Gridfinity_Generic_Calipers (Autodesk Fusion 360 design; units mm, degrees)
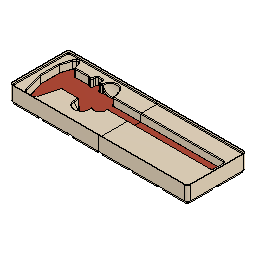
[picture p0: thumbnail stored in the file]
work_plane "WorkPlane1" AlongDistance 0
sketch "Base plate sketch" plane through (0, 0, 0) normal (0, 0, 1) x axis (1, 0, 0)
  line L1 (41.75, -0.25) -> (-0.25, -0.25)
  line L2 (41.75, 41.75) -> (41.75, -0.25)
  line L3 (-0.25, 41.75) -> (41.75, 41.75)
  line L4 (-0.25, -0.25) -> (-0.25, 41.75)
  point P1 (0, 0)
  point P2 (-0.25, -0.25)
  point P5 (-0.25, 41.75)
  point P3 (41.75, -0.25)
  point P4 (41.75, 41.75)
  horizontal L1
  vertical L2
  horizontal L3
  vertical L4
  dimension "d26" distance P1 P2 = 0.25
  dimension "d27" distance P1 P5 = 0.25
  dimension "d28" distance P2 P3 = 42
  dimension "d29" distance P3 P4 = 42
extrude "Extrude1" new body sketch "Base plate sketch" against normal blind 2.4 (magnitude of "-( 2.40 mm )") bodies "Base"
fillet "Fillet1" radius 4
chamfer "Chamfer1" distance 2.4
extrude "Extrude2" add of existing geometry blind 2.6
chamfer "Chamfer2" distance 0.8
rectangular_pattern "R-Pattern1" uSpaceDistance 42 vSpaceDistance 42 bodies "Base (1)", "Base (2)", "Base (3)", "Base (4)", "Base (5)", "Base (6)", "Base (7)", "Base (8)"
sketch "Simple box sketch" plane through (0, 0, 0) normal (0, 0, 1) x axis (1, 0, 0)
  line L1 (251.5, 0) -> (0, 0)
  line L2 (251.5, 83.5) -> (251.5, 0)
  line L3 (0, 83.5) -> (251.5, 83.5)
  line L4 (0, 0) -> (0, 83.5)
  point P1 (0, 0)
  point P2 (0, 0)
  point P3 (251.5, 0)
  point P4 (251.5, 83.5)
  horizontal L1
  vertical L2
  horizontal L3
  vertical L4
  coincident P1 L4
  coincident P1 L1
  dimension "d42" distance P2 P3 = 251.5
  dimension "d43" distance P3 P4 = 83.5
extrude "Extrude3" new body sketch "Simple box sketch" along normal blind 16
fillet "Fillet2" radius 3.75
work_plane "WorkPlane2" AlongDistance 16
sketch "Simple box at point sketch" plane through (0, 0, 16) normal (0, 0, 1) x axis (1, 0, 0)
  line L1 (251.5, 0) -> (0, 0)
  line L2 (251.5, 83.5) -> (251.5, 0)
  line L3 (0, 83.5) -> (251.5, 83.5)
  line L4 (0, 0) -> (0, 83.5)
  point P1 (0, 0)
  point P2 (0, 0)
  point P3 (251.5, 0)
  point P4 (251.5, 83.5)
  horizontal L1
  vertical L2
  horizontal L3
  vertical L4
  coincident P1 L4
  coincident P1 L1
  dimension "d49" distance P2 P3 = 251.5
  dimension "d50" distance P3 P4 = 83.5
extrude "Extrude4" new body sketch "Simple box at point sketch" along normal blind 4.4 bodies "Lip body"
fillet "Fillet3" radius 3.75
work_plane "WorkPlane3" AlongDistance 21
sketch "Base plate sketch (1)" plane through (0, 0, 21) normal (0, 0, 1) x axis (1, 0, 0)
  line L1 (252, -0.5) -> (-0.5, -0.5)
  line L2 (252, 84) -> (252, -0.5)
  line L3 (-0.5, 84) -> (252, 84)
  line L4 (-0.5, -0.5) -> (-0.5, 84)
  point P1 (0, 0)
  point P2 (-0.5, -0.5)
  point P5 (-0.5, 84)
  point P3 (252, -0.5)
  point P4 (252, 84)
  horizontal L1
  vertical L2
  horizontal L3
  vertical L4
  dimension "d56" distance P1 P2 = 0.5
  dimension "d57" distance P1 P5 = 0.5
  dimension "d58" distance P2 P3 = 252.5
  dimension "d59" distance P3 P4 = 84.5
extrude "Extrude5" new body sketch "Base plate sketch (1)" against normal blind 2.4 (magnitude of "-( 2.40 mm )") bodies "Lip cutout"
fillet "Fillet4" radius 4.25
chamfer "Chamfer3" distance 2.4
extrude "Extrude6" add of existing geometry blind 2.6
work_plane "WorkPlane4" AlongDistance 0
sketch "Lip top chamfer" plane through (0, 0, 20.4) normal (0, 0, 1) x axis (1, 0, 0)
  line L1 (251.5, 0) -> (0, 0)
  line L2 (251.5, 83.5) -> (251.5, 0)
  line L3 (0, 83.5) -> (251.5, 83.5)
  line L4 (0, 0) -> (0, 83.5)
  point P1 (0, 0)
  point P2 (0, 0)
  point P3 (251.5, 0)
  point P4 (251.5, 83.5)
  horizontal L1
  vertical L2
  horizontal L3
  vertical L4
  coincident P1 L4
  coincident P1 L1
  dimension "d68" distance P2 P3 = 251.5
  dimension "d69" distance P3 P4 = 83.5
extrude "Extrude7" new body sketch "Lip top chamfer" against normal blind 0.6 (magnitude of "-( 0.60 mm )")
combine "Combine1" bodies "Lip cutout"
work_plane "WorkPlane5" AlongDistance 16
sketch "Simple box at point sketch (1)" plane through (0, 0, 16) normal (0, 0, 1) x axis (1, 0, 0)
  line L1 (250.3, 1.2) -> (1.2, 1.2)
  line L2 (250.3, 82.3) -> (250.3, 1.2)
  line L3 (1.2, 82.3) -> (250.3, 82.3)
  line L4 (1.2, 1.2) -> (1.2, 82.3)
  point P1 (0, 0)
  point P2 (1.2, 1.2)
  point P5 (1.2, 82.3)
  point P3 (250.3, 1.2)
  point P4 (250.3, 82.3)
  horizontal L1
  vertical L2
  horizontal L3
  vertical L4
  dimension "d73" distance P1 P2 = 1.2
  dimension "d74" distance P1 P5 = 1.2
  dimension "d75" distance P2 P3 = 249.1
  dimension "d76" distance P3 P4 = 81.1
extrude "Extrude8" new body sketch "Simple box at point sketch (1)" along normal blind 2.55
fillet "Fillet5" radius 2.55
chamfer "Chamfer4" distance 2.55
combine "Combine2"
combine "Combine3" bodies "Lip body"
work_plane "WorkPlane6" AlongDistance 0
sketch "Base clearance cut sketch" plane through (0, 0, 0) normal (0, 0, 1) x axis (1, 0, 0)
  line L1 (247.75, 0) -> (3.75, 0)
  line L2 (251.5, 79.75) -> (251.5, 3.75)
  line L3 (3.75, 83.5) -> (247.75, 83.5)
  line L4 (0, 3.75) -> (0, 79.75)
  line L5 (261.5, 79.75) -> (261.5, 3.75)
  line L6 (3.75, 93.5) -> (247.75, 93.5)
  line L7 (-10, 3.75) -> (-10, 79.75)
  line L8 (247.75, -10) -> (3.75, -10)
  arc A1 centre (247.75, 3.75) radius 3.75 clockwise from (251.5, 3.75) to (247.75, 0)
  arc A2 centre (247.75, 79.75) radius 3.75 clockwise from (247.75, 83.5) to (251.5, 79.75)
  arc A3 centre (3.75, 79.75) radius 3.75 clockwise from (0, 79.75) to (3.75, 83.5)
  arc A4 centre (3.75, 3.75) radius 3.75 clockwise from (3.75, 0) to (0, 3.75)
  arc A5 centre (247.75, 3.75) radius 13.75 clockwise from (261.5, 3.75) to (247.75, -10)
  arc A6 centre (247.75, 79.75) radius 13.75 clockwise from (247.75, 93.5) to (261.5, 79.75)
  arc A7 centre (3.75, 79.75) radius 13.75 clockwise from (-10, 79.75) to (3.75, 93.5)
  arc A8 centre (3.75, 3.75) radius 13.75 clockwise from (3.75, -10) to (-10, 3.75)
  point P1 (0, 0)
  point P3 (251.5, 0)
  point P4 (251.5, 83.5)
  point P2 (0, 0)
  horizontal L1
  vertical L2
  horizontal L3
  vertical L4
  coincident P1 L4
  coincident P1 L1
  coincident P3 L1
  coincident P3 L2
  tangent L1 A1
  tangent L2 A1
  coincident P4 L2
  coincident P4 L3
  tangent L2 A2
  tangent L3 A2
  tangent L3 A3
  tangent L4 A3
  coincident P2 L4
  coincident P2 L1
  tangent L4 A4
  tangent L1 A4
  equal A1 A2
  equal A2 A3
  equal A3 A4
  dimension "d83" distance P2 P3 = 251.5
  dimension "d84" distance P3 P4 = 83.5
  dimension "d85" radius A1 = 3.75
  dimension "d86" = 10
extrude "Extrude9" cut sketch "Base clearance cut sketch" along normal blind 1000 and against normal blind 1000
combine "Combine4" bodies "Base (1)", "Base (2)", "Base (3)", "Base (4)", "Base (5)", "Base (6)", "Base (7)", "Base (8)"
canvas "Canvas1"
sketch "Sketch1" plane through (0, 0, 16) normal (0, 0, 1) x axis (1, 0, 0)
  line L1 (-92.5619, 18.2001) -> (-95.3903, 21.0285)
  line L2 (-89.9737, 8.5409) -> (-92.5619, 18.2001)
  line L3 (-68.9737, 8.5409) -> (-89.9737, 8.5409)
  line L4 (-67.9737, 7.5409) -> (-68.9737, 8.5409)
  line L5 (-61.9737, 7.5409) -> (-67.9737, 7.5409)
  line L6 (-61.9737, 14.5409) -> (-61.9737, 7.5409)
  line L7 (-54.9737, 14.5409) -> (-61.9737, 14.5409)
  line L8 (-54.9737, 7.5409) -> (-54.9737, 14.5409)
  line L9 (-48.9737, 7.5409) -> (-54.9737, 7.5409)
  line L10 (-47.9737, 8.5409) -> (-48.9737, 7.5409)
  line L11 (-27.9737, 8.5409) -> (-47.9737, 8.5409)
  line L12 (-98.6042, 17.1983) -> (-95.3903, 21.0285)
  line L13 (-102.9923, 3.6933) -> (-98.6042, 17.1983)
  line L14 (-102.9923, -22.5992) -> (-102.9923, 3.6933)
  line L15 (-95.309, -50.1366) -> (-102.9923, -22.5992)
  line L16 (-88.4425, -55.2852) -> (-95.309, -50.1366)
  line L17 (-82.0045, -50.1033) -> (-88.4425, -55.2852)
  line L18 (-74.757, -22.5735) -> (-82.0045, -50.1033)
  line L19 (-50.257, -22.5735) -> (-74.757, -22.5735)
  curve K1 (-28.5837, -23.1562) -> (-50.257, -22.5735)
  line L20 (-18.4991, -15.952) -> (131.0263, -15.952)
  line L21 (131.0263, 0.048) -> (131.0263, -15.952)
  line L22 (-27.9737, 0.048) -> (131.0263, 0.048)
  line L23 (-27.9737, 8.5409) -> (-27.9737, 0.048)
  curve K2 (-28.0801, -24.0202) -> (-50.2799, -23.5735)
  line L24 (-50.2799, -23.5735) -> (-73.9862, -23.5735)
  line L25 (-73.9862, -23.5735) -> (-81.1212, -50.676)
  line L26 (-81.1212, -50.676) -> (-88.4207, -56.5514)
  line L27 (-88.4207, -56.5514) -> (-96.1809, -50.7327)
  line L28 (-96.1809, -50.7327) -> (-103.9923, -22.7361)
  line L29 (-103.9923, -22.7361) -> (-103.9923, 3.8517)
  line L30 (-103.9923, 3.8517) -> (-99.4952, 17.6922)
  line L31 (-99.4952, 17.6922) -> (-95.4549, 22.5073)
  line L32 (-91.6653, 18.7177) -> (-95.4549, 22.5073)
  line L33 (-89.2064, 9.5409) -> (-91.6653, 18.7177)
  line L34 (-68.5595, 9.5409) -> (-89.2064, 9.5409)
  line L35 (-67.5595, 8.5409) -> (-68.5595, 9.5409)
  line L36 (-62.9737, 8.5409) -> (-67.5595, 8.5409)
  line L37 (-62.9737, 15.5409) -> (-62.9737, 8.5409)
  line L38 (-53.9737, 15.5409) -> (-62.9737, 15.5409)
  line L39 (-53.9737, 8.5409) -> (-53.9737, 15.5409)
  line L40 (-49.3879, 8.5409) -> (-53.9737, 8.5409)
  line L41 (-48.3879, 9.5409) -> (-49.3879, 8.5409)
  line L42 (-26.9737, 9.5409) -> (-48.3879, 9.5409)
  line L43 (-26.9737, 9.5409) -> (-26.9737, 1.048)
  line L44 (-26.9737, 1.048) -> (132.0263, 1.048)
  line L45 (132.0263, 1.048) -> (132.0263, -16.952)
  line L46 (-18.7439, -16.952) -> (132.0263, -16.952)
  line L47 (-38.5837, 9.6319) -> (-38.5837, -30.3681)
  line L48 (-28.5837, 9.6319) -> (-28.5837, -30.3681)
  line L49 (-48.5837, 9.6319) -> (-48.5837, -30.3681)
  line L50 (-38.5837, -40.3681) -> (-38.5837, -30.3681)
  line L51 (-38.5837, 19.6319) -> (-38.5837, 9.6319)
  line L52 (135.75, -57.8) -> (-108.25, -57.8)
  line L53 (138.3, 20.75) -> (138.3, -55.25)
  line L54 (-108.25, 23.3) -> (135.75, 23.3)
  line L55 (-110.8, -55.25) -> (-110.8, 20.75)
  circle C1 centre (-23.0682, -20.2165) radius 6.25
  circle C2 centre (-23.0682, -20.2165) radius 7.25
  circle C3 centre (-38.5837, -30.3681) radius 10
  circle C4 centre (-38.5837, 9.6319) radius 10
  arc A1 centre (135.75, -55.25) radius 2.55 clockwise from (138.3, -55.25) to (135.75, -57.8)
  arc A2 centre (135.75, 20.75) radius 2.55 clockwise from (135.75, 23.3) to (138.3, 20.75)
  arc A3 centre (-108.25, 20.75) radius 2.55 clockwise from (-110.8, 20.75) to (-108.25, 23.3)
  arc A4 centre (-108.25, -55.25) radius 2.55 clockwise from (-108.25, -57.8) to (-110.8, -55.25)
  point P26 (-28.5837, -23.1562)
  point P29 (-18.4991, -15.952)
  point P58 (-38.5837, -30.3681)
  point P59 (-38.5837, -30.3681)
  point P60 (-38.5837, 9.6319)
  point P61 (-38.5837, 9.6319)
  point P63 (-28.5837, 9.6319)
  point P65 (-48.5837, 9.6319)
  point P64 (-48.5837, -30.3681)
  point P62 (-28.5837, -30.3681)
  point P66 (-38.5837, -30.3681)
  point P67 (-38.5837, -40.3681)
  point P68 (-38.5837, 9.6319)
  point P69 (-38.5837, 19.6319)
  point P9 (-54.9737, 14.5409)
  point P10 (-54.9737, 7.5409)
  point P8 (-61.9737, 14.5409)
  point P11 (-48.9737, 7.5409)
  point P6 (-67.9737, 7.5409)
  point P7 (-61.9737, 7.5409)
  point P5 (-68.9737, 8.5409)
  point P4 (-89.9737, 8.5409)
  point P12 (-47.9737, 8.5409)
  point P13 (-27.9737, 8.5409)
  point P3 (-92.5619, 18.2001)
  point P2 (-95.3903, 21.0285)
  point P14 (-98.6042, 17.1983)
  point P15 (-102.9923, 3.6933)
  point P20 (-74.757, -22.5735)
  point P21 (-50.257, -22.5735)
  point P28 (131.0263, -15.952)
  point P30 (131.0263, 0.048)
  point P31 (-27.9737, 0.048)
  horizontal L3
  parallel L3 L5
  perpendicular L5 L6
  perpendicular L6 L7
  perpendicular L7 L8
  perpendicular L8 L9
  perpendicular L8 L11
  collinear L5 L9
  vertical L14
  horizontal L19
  coincident P26 C1
  coincident C1 P29
  horizontal L20
  perpendicular L20 L21
  perpendicular L21 L22
  vertical L23
  coincident P58 P59
  vertical L47
  coincident P60 P61
  equal C3 C4
  coincident C4 P63
  coincident C4 P65
  coincident C3 P64
  coincident C3 P62
  coincident P58 P66
  coincident C3 P67
  parallel L47 L50
  coincident P61 P68
  coincident C4 P69
  perpendicular L42 L51
  coincident P26 L48
  dimension "d1" distance L9 L11 = 1
  dimension "d2" distance P9 P10 = 7
  dimension "d3" distance P8 P9 = 7
  dimension "d4" distance P10 P11 = 6
  dimension "d5" distance P6 P7 = 6
  dimension "d6" distance P5 P6 = 1 (= "d1")
  dimension "d7" distance P4 P5 = 21
  dimension "d8" angle L4 L5 = 135
  dimension "d9" angle L9 L10 = 135
  dimension "d10" distance P12 P13 = 20
  dimension "d11" angle L2 L3 = 105
  dimension "d12" angle L1 L2 = 150
  dimension "d13" distance P3 P4 = 10
  dimension "d14" distance P2 P3 = 4
  dimension "d15" angle L1 L12 = 85
  dimension "d16" distance P2 P14 = 5
  dimension "d17" angle L12 L13 = 158
  dimension "d18" distance P14 P15 = 14.2
  dimension "d19" distance P20 P21 = 24.5
  dimension "d20" diameter C1 = 12.5
  dimension "d21" distance P28 P30 = 16
  dimension "d22" distance P30 P31 = 159
  dimension "d24" = 1
  dimension "d94" = 1
  dimension "d95" diameter C3 = 20
  dimension "d96" = 10 (= "d95 / 2")
  dimension "d97" = -10 (= "-d96")
  dimension "d98" distance P59 P60 = 40
extrude "Extrude1" cut sketch "Sketch1" profile of C2 L30 L27 L26 L35 L34 K2 L31 L32 L25 L24 L36 L29 L45 L42 L40 L37 L28 L38 L39 L44 L46 L43 L33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 against normal blind 11
fillet "Fillet6" radius 2
revolve "Revolve1" sketch "Sketch1" AlongAngle 360
fillet "Fillet7" radius 1
fillet "Fillet8" radius 1
extrude "Extrude2" new body of existing geometry blind 0.8
offset_faces "OffsetFaces1" distance -0.2
chamfer "Chamfer1" distance 0.2
copy_paste_bodies "CutPasteBodies"
work_plane "WorkPlane1" AlongDistance -125.75 (= "-( ( 251.5 / 2 ) * 1 mm )")
split "Split1" bodies "Gridfinity bin 2x6x3 (1)"
split "Split1"
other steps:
base_feature "Base Feature"
extrude "Extrude10" cut sketch "Sketch1" profile of C2 L30 L27 L26 L35 L34 K2 L31 L32 L25 L24 L36 L29 L45 L42 L40 L37 L28 L38 L39 L44 L46 L43 L33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 against normal blind 11
create_component "CreateComponent1"
create_component "CreateComponent2"
remove_body "RemoveBody1"
named bodies: "Base", "Base (1)", "Base (2)", "Base (3)", "Base (4)", "Base (5)", "Base (6)", "Base (7)", "Base (8)", "Base (9)", "Base (10)", "Base (11)", "Gridfinity bin 2x6x3", "Lip body", "Lip cutout", "Gridfinity bin 2x6x3 (1)"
